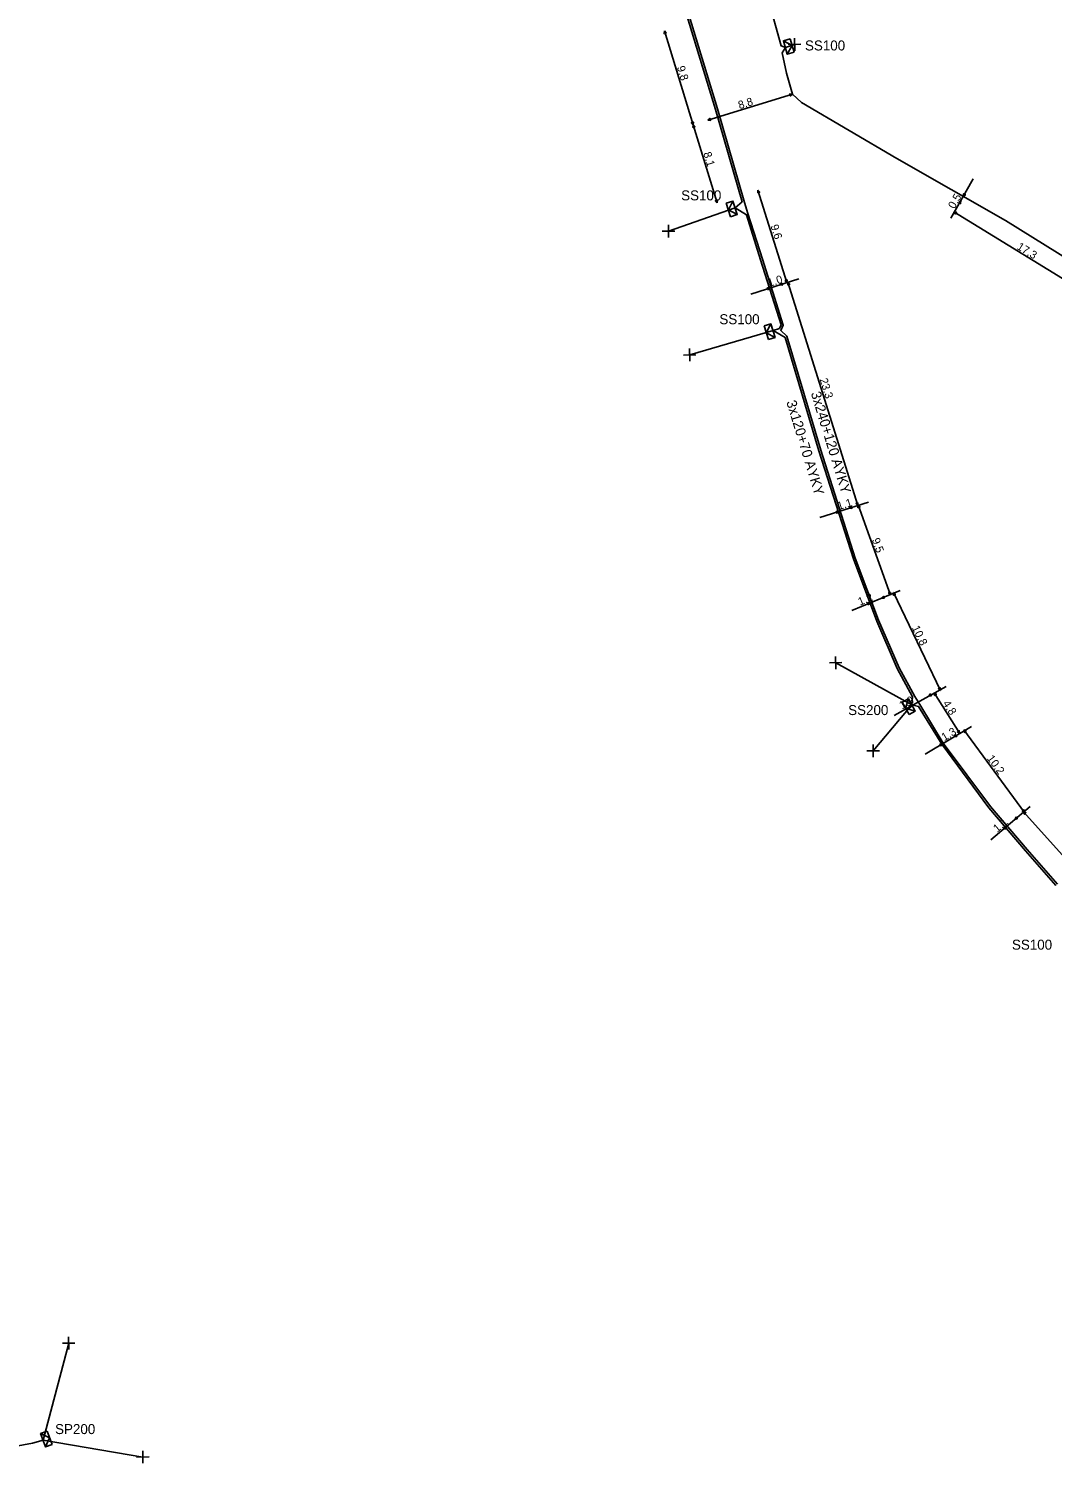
# Model space of a CAD drawing. Extents: x -762504 to -761250, y -1152974 to -1152253.
# Drawn here: x -761447.4 to -761345.8, y -1152510.4 to -1152367.8 of the extents above; entities that cross this region are included whole.
import ezdxf

# ---------------------------------------------------------------- set-up
doc = ezdxf.new("R2010")
doc.units = 0
for name, color, linetype in [('Vrstva 31', 7, 'Continuous'), ('Vrstva 33', 7, 'Continuous'), ('Vrstva 34', 7, 'Continuous'), ('Vrstva 40', 7, 'Continuous'), ('Vrstva 5', 7, 'Continuous'), ('Vrstva 59', 7, 'Continuous'), ('Vrstva 6', 7, 'Continuous')]:
    doc.layers.add(name, color=color, linetype=linetype)

msp = doc.modelspace()

# ---------------------------------------------------------------- linework, layer by layer
at = {"layer": 'Vrstva 31'}
for points in [[(-761371.413, -1152370.163), (-761372.086, -1152370.356), (-761372.472, -1152369.01), (-761371.799, -1152368.817)], [(-761371.606, -1152369.49), (-761372.472, -1152369.01)], [(-761371.413, -1152370.163), (-761371.799, -1152368.817)], [(-761371.606, -1152369.49), (-761372.086, -1152370.356)], [(-761378.153, -1152385.168), (-761377.487, -1152384.952), (-761377.055, -1152386.283), (-761377.72, -1152386.5)], [(-761377.937, -1152385.834), (-761377.487, -1152384.952)], [(-761378.153, -1152385.168), (-761377.72, -1152386.5)], [(-761377.937, -1152385.834), (-761377.055, -1152386.283)], [(-761374.375, -1152397.363), (-761373.706, -1152397.158), (-761373.297, -1152398.497), (-761373.966, -1152398.701)], [(-761374.375, -1152397.363), (-761373.966, -1152398.701)], [(-761374.171, -1152398.032), (-761373.706, -1152397.158)], [(-761374.171, -1152398.032), (-761373.297, -1152398.497)], [(-761360.673, -1152434.755), (-761360.061, -1152434.415), (-761359.382, -1152435.64), (-761359.995, -1152435.979)], [(-761360.673, -1152434.755), (-761359.995, -1152435.979)], [(-761360.334, -1152435.367), (-761360.061, -1152434.415)], [(-761360.334, -1152435.367), (-761359.382, -1152435.64)], [(-761445.121, -1152508.541), (-761445.779, -1152508.78), (-761446.258, -1152507.465), (-761445.6, -1152507.225)], [(-761445.361, -1152507.883), (-761446.258, -1152507.465)], [(-761445.121, -1152508.541), (-761445.6, -1152507.225)], [(-761445.361, -1152507.883), (-761445.779, -1152508.78)]]:
    msp.add_lwpolyline(points, dxfattribs=at)
at = {"layer": 'Vrstva 34'}
for points in [[(-761371.985, -1152369.391), (-761370.735, -1152369.369)], [(-761371.349, -1152370.005), (-761371.371, -1152368.755)], [(-761383.879, -1152388.565), (-761383.901, -1152387.315)], [(-761384.515, -1152387.951), (-761383.265, -1152387.929)], [(-761382.405, -1152400.251), (-761381.155, -1152400.229)], [(-761381.769, -1152400.865), (-761381.791, -1152399.615)], [(-761367.269, -1152431.465), (-761367.291, -1152430.215)], [(-761367.905, -1152430.851), (-761366.655, -1152430.829)], [(-761363.549, -1152440.225), (-761363.571, -1152438.975)], [(-761364.185, -1152439.611), (-761362.935, -1152439.589)], [(-761444.095, -1152498.481), (-761442.845, -1152498.459)], [(-761443.459, -1152499.095), (-761443.481, -1152497.845)], [(-761436.725, -1152509.801), (-761435.475, -1152509.779)], [(-761436.089, -1152510.415), (-761436.111, -1152509.165)]]:
    msp.add_lwpolyline(points, dxfattribs=at)
at = {"layer": 'Vrstva 40'}
for points in [[(-761384.3, -1152368.028), (-761384.124, -1152368.232), (-761384.323, -1152368.297)], [(-761371.578, -1152374.329), (-761371.782, -1152374.505), (-761371.846, -1152374.306)], [(-761381.43, -1152377.363), (-761381.606, -1152377.158), (-761381.407, -1152377.094)], [(-761381.43, -1152377.357), (-761381.254, -1152377.561), (-761381.453, -1152377.626)], [(-761379.972, -1152376.91), (-761379.768, -1152376.734), (-761379.704, -1152376.933)], [(-761379.05, -1152385.123), (-761379.226, -1152384.918), (-761379.027, -1152384.854)], [(-761375.001, -1152383.857), (-761374.825, -1152384.062), (-761375.023, -1152384.126)], [(-761354.849, -1152384.928), (-761354.878, -1152385.196), (-761355.061, -1152385.094)], [(-761354.601, -1152384.492), (-761354.572, -1152384.224), (-761354.389, -1152384.325)], [(-761355.532, -1152386.029), (-761355.265, -1152386.067), (-761355.373, -1152386.247)], [(-761373.798, -1152393.589), (-761374.002, -1152393.766), (-761374.066, -1152393.567)], [(-761372.842, -1152393.291), (-761372.638, -1152393.115), (-761372.574, -1152393.314)], [(-761372.119, -1152393.062), (-761372.296, -1152392.858), (-761372.097, -1152392.794)], [(-761372.021, -1152393.007), (-761371.844, -1152393.212), (-761372.043, -1152393.276)], [(-761365.089, -1152415.222), (-761365.266, -1152415.018), (-761365.067, -1152414.954)], [(-761366.947, -1152415.8), (-761367.152, -1152415.976), (-761367.216, -1152415.777)], [(-761365.932, -1152415.48), (-761365.728, -1152415.304), (-761365.664, -1152415.503)], [(-761365.06, -1152415.157), (-761364.877, -1152415.355), (-761365.074, -1152415.426)], [(-761363.837, -1152424.889), (-761364.025, -1152425.082), (-761364.107, -1152424.89)], [(-761362.722, -1152424.421), (-761362.534, -1152424.227), (-761362.453, -1152424.42)], [(-761361.839, -1152424.112), (-761362.022, -1152423.914), (-761361.826, -1152423.843)], [(-761361.551, -1152423.858), (-761361.348, -1152424.035), (-761361.536, -1152424.127)], [(-761356.869, -1152433.602), (-761357.072, -1152433.425), (-761356.884, -1152433.333)], [(-761358.042, -1152434.161), (-761357.879, -1152433.946), (-761357.775, -1152434.127)], [(-761357.491, -1152433.818), (-761357.271, -1152433.973), (-761357.448, -1152434.084)], [(-761359.708, -1152435.089), (-761359.871, -1152435.304), (-761359.975, -1152435.123)], [(-761354.959, -1152437.872), (-761355.179, -1152437.717), (-761355.002, -1152437.606)], [(-761354.551, -1152437.498), (-761354.318, -1152437.633), (-761354.485, -1152437.759)], [(-761356.658, -1152438.889), (-761356.817, -1152439.106), (-761356.924, -1152438.927)], [(-761355.512, -1152438.211), (-761355.353, -1152437.993), (-761355.245, -1152438.172)], [(-761349.482, -1152446.421), (-761349.363, -1152446.179), (-761349.226, -1152446.337)], [(-761348.518, -1152445.712), (-761348.751, -1152445.576), (-761348.584, -1152445.451)], [(-761348.632, -1152445.648), (-761348.386, -1152445.758), (-761348.538, -1152445.901)], [(-761350.338, -1152447.148), (-761350.457, -1152447.39), (-761350.594, -1152447.232)]]:
    msp.add_lwpolyline(points, close=True, dxfattribs=at)
for points in [[(-761384.3, -1152368.03), (-761381.43, -1152377.36)], [(-761379.97, -1152376.91), (-761371.58, -1152374.33)], [(-761381.43, -1152377.36), (-761379.05, -1152385.12)], [(-761353.61, -1152382.75), (-761355.84, -1152386.66)], [(-761372.12, -1152393.06), (-761375, -1152383.86)], [(-761340.81, -1152395.06), (-761355.53, -1152386.03)], [(-761375.71, -1152394.19), (-761370.93, -1152392.69)], [(-761372.02, -1152393.01), (-761365.09, -1152415.22)], [(-761368.86, -1152416.39), (-761364.02, -1152414.88)], [(-761361.84, -1152424.11), (-761365.06, -1152415.16)], [(-761360.87, -1152423.65), (-761365.69, -1152425.65)], [(-761356.87, -1152433.6), (-761361.55, -1152423.86)], [(-761356.29, -1152433.19), (-761361.46, -1152436.07)], [(-761357.49, -1152433.82), (-761354.96, -1152437.87)], [(-761358.38, -1152439.92), (-761353.79, -1152437.19)], [(-761354.55, -1152437.5), (-761348.52, -1152445.71)], [(-761347.95, -1152445.13), (-761351.87, -1152448.44)], [(-761340.33, -1152454.86), (-761348.63, -1152445.65)]]:
    msp.add_lwpolyline(points, dxfattribs=at)
at = {"layer": 'Vrstva 5'}
for points in [[(-761339.83, -1152393.47), (-761350.42, -1152386.88), (-761361.2, -1152380.72), (-761370.69, -1152375.16), (-761371.58, -1152374.33), (-761372.15, -1152372.25), (-761372.61, -1152370.21), (-761372.28, -1152369.68), (-761372.68, -1152369.52), (-761373.98, -1152364.86)], [(-761345.4, -1152452.99), (-761348.42, -1152449.52), (-761352.06, -1152445.25), (-761356.75, -1152438.94), (-761359.04, -1152435.18), (-761359.72, -1152435.03), (-761359.65, -1152434.23), (-761361.16, -1152431.41), (-761363.19, -1152426.7), (-761365.52, -1152420.5), (-761368.95, -1152409.77), (-761372.29, -1152398.52), (-761373.5, -1152397.83), (-761372.87, -1152397.62), (-761372.71, -1152397.25), (-761374.75, -1152390.79), (-761376.15, -1152386.31), (-761377.26, -1152385.62), (-761376.58, -1152385.02), (-761379.23, -1152375.84), (-761382.4, -1152365.41)], [(-761345.24, -1152452.86), (-761348.26, -1152449.4), (-761351.9, -1152445.13), (-761356.59, -1152438.82), (-761358.92, -1152434.98), (-761359.43, -1152434.2), (-761360.98, -1152431.33), (-761363.01, -1152426.62), (-761365.33, -1152420.44), (-761368.75, -1152409.71), (-761372.13, -1152398.38), (-761372.73, -1152397.8), (-761372.49, -1152397.27), (-761374.56, -1152390.73), (-761375.99, -1152386.17), (-761376.34, -1152385.1), (-761379.03, -1152375.78), (-761382.2, -1152365.35)], [(-761458.57, -1152508.96), (-761457.11, -1152508.68), (-761455.14, -1152508.7), (-761451.22, -1152508.72), (-761448.85, -1152508.73), (-761447.08, -1152508.42), (-761446.02, -1152508.12)]]:
    msp.add_lwpolyline(points, dxfattribs=at)
at = {"layer": 'Vrstva 59'}
for points in [[(-761372.28, -1152369.68), (-761371.36, -1152369.38)], [(-761377.27, -1152385.62), (-761383.89, -1152387.94)], [(-761373.5, -1152397.83), (-761381.78, -1152400.24)], [(-761359.72, -1152435.03), (-761367.28, -1152430.84)], [(-761359.72, -1152435.03), (-761363.56, -1152439.6)], [(-761446.02, -1152508.12), (-761443.47, -1152498.47)], [(-761446.02, -1152508.12), (-761436.1, -1152509.79)]]:
    msp.add_lwpolyline(points, dxfattribs=at)

# ---------------------------------------------------------------- texts
at = {"layer": 'Vrstva 33'}
for s, p in [('SS100', (-761370.33, -1152369.98)), ('SS100', (-761382.63, -1152384.88)), ('SS100', (-761378.83, -1152397.19)), ('SS200', (-761366.04, -1152436.04)), ('SS100', (-761349.77, -1152459.36)), ('SP200', (-761444.82, -1152507.51))]:
    msp.add_text(s, height=0.9943, dxfattribs=at).set_placement(p)
at = {"layer": 'Vrstva 40'}
for s, rotation, p in [('9,8', 287.06111, (-761383.06, -1152371.64)), ('8,8', 17.06862, (-761376.83, -1152375.82)), ('8,1', 287.06149, (-761380.44, -1152380.19)), ('0,5', 60.25512, (-761355.48, -1152385.79)), ('9,6', 287.38399, (-761373.76, -1152387.41)), ('17,3', 328.48351, (-761349.35, -1152389.68)), ('1,0', 17.38727, (-761373.89, -1152393.49)), ('23,3', 287.32508, (-761368.88, -1152402.68)), ('1,1', 17.38737, (-761366.98, -1152415.68)), ('9,5', 289.77922, (-761363.7, -1152418.6)), ('1,2', 22.53272, (-761364.87, -1152425.18)), ('10,8', 295.63107, (-761359.73, -1152427.36)), ('1,9', 29.06572, (-761360.7, -1152435.5)), ('4,8', 301.99127, (-761356.68, -1152434.88)), ('1,3', 30.70263, (-761356.49, -1152438.65)), ('10,2', 306.32094, (-761352.3, -1152440.36)), ('1,1', 40.23659, (-761351.23, -1152447.74))]:
    msp.add_text(s, height=0.7954, rotation=rotation, dxfattribs=at).set_placement(p)
at = {"layer": 'Vrstva 6'}
for s, rotation, p in [('3x120+70 AYKY', 286.91649, (-761372.19, -1152404.92)), ('3x240+120 AYKY', 286.98686, (-761369.76, -1152404.04))]:
    msp.add_text(s, height=0.99429, rotation=rotation, dxfattribs=at).set_placement(p)

doc.saveas('drawing.dxf')
